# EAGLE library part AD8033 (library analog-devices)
2.7 V, 800 ?A, 80 MHz Rail-to-Rail I/O Amplifiers Source: http://www.analog.com/static/imported-files/data_sheets/AD8031_8032.pdf
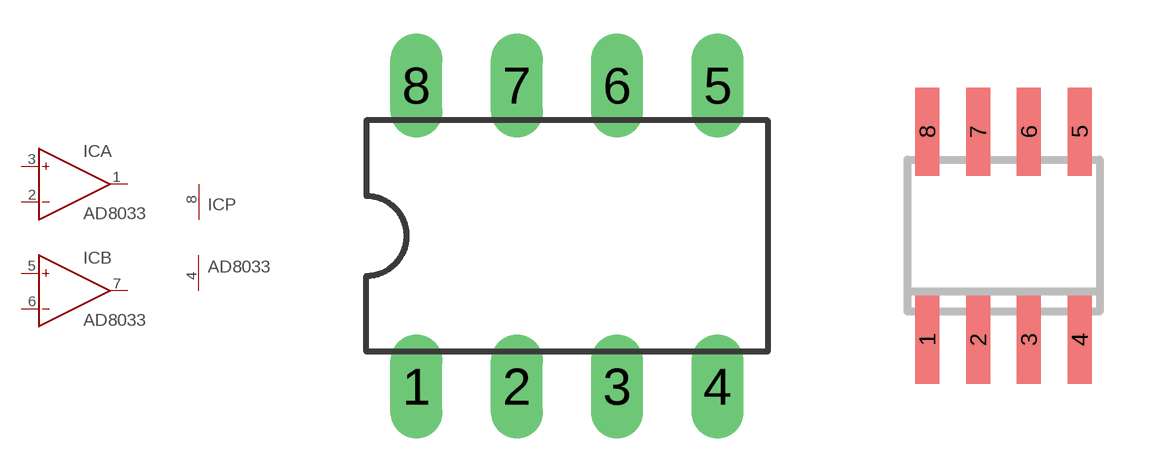
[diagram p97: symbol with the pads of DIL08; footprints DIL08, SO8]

Designator prefix IC; gates A=OP B=OP P=PWR+-

## AD8033N (OC_FARNELL: unknown; OC_NEWARK: unknown)  [DIL08]
1  A:OUT  out
2  A:IN-  in
3  A:IN+  in
4  P:V-  pwr
5  B:IN+  in
6  B:IN-  in
7  B:OUT  out
8  P:V+  pwr

## AD8033R (MF: ALTERA CORPORATION; MPN: AD8033ARZ; OC_FARNELL: 8621519; OC_NEWARK: 59K6245)  [SO8]
Pads as for DIL08

## AD8033RM (MF: ALTERA CORPORATION; MPN: AD8033ARZ-REEL; OC_FARNELL: 8621519; OC_NEWARK: 59K6246)  [MSOP08]
Pads as for DIL08

## Footprint DIL08 (pad centres in mm)
Dual In Line Package
drill 0.813 long: 1 -3.81,-3.81; 2 -1.27,-3.81; 3 1.27,-3.81; 4 3.81,-3.81; 5 3.81,3.81; 6 1.27,3.81; 7 -1.27,3.81; 8 -3.81,3.81

## Footprint SO8 (pad centres in mm)
8-Lead Small Outline IC (SO-8) Source: http://www.analog.com/UploadedFiles/Data_Sheets/703465986AD8611_2_0.pdf
smd 0.6 x 2.2: 1 -1.905,-2.6; 2 -0.635,-2.6; 3 0.635,-2.6; 4 1.905,-2.6; 5 1.905,2.6; 6 0.635,2.6; 7 -0.635,2.6; 8 -1.905,2.6

## Footprint MSOP08 (pad centres in mm)
8-Lead micro SO (RM-8) Source: http://www.analog.com/UploadedFiles/Data_Sheets/703465986AD8611_2_0.pdf
smd 0.4 x 1: 1 -0.976,-2.263; 2 -0.326,-2.263; 3 0.324,-2.263; 4 0.974,-2.263; 5 0.974,2.262; 6 0.324,2.262; 7 -0.326,2.262; 8 -0.976,2.262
